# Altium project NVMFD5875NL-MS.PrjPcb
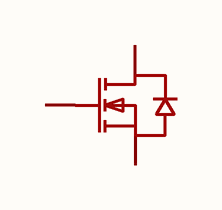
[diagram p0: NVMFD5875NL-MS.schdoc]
1 sheet, 1 parts. Net scope: global (net labels, ports and power ports of the same name join across sheets).

## Sheet NVMFD5875NL-MS.schdoc
size 127 x 101 mm

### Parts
Q?  nvmfd5875nl-ms  [TDSON-8-4_IPG20N06S4L26]  (value not drawn)  (part A of 2)

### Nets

Not connected (* = marked no-connect by the designer): Q? 1(S) 2(G) 6(D)

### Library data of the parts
Q? = nvmfd5875nl-ms: 数量:2个N沟道;漏源电压(Vdss):60V;连续漏极电流(Id):35A;导通电阻(RDS(on)):11mΩ@10V;耗散功率(Pd):60W;阈值电压(Vgs(th)):1.6V;; Manufacturer: MSKSEMI(美森科); AddInBom: yes; ModelId: 7b57ce7acef9460a94d25fd72c475b45; ModelTransform: 212.9917,253.9365,0,270,0,0,36.811,0,0; Number: 2个N沟道; Drain to Source Voltage: 60V; Current - Continuous Drain(Id): 35A; Pd - Power Dissipation: 60W; Gate Threshold Voltage (Vgs(th)): 1.6V; Gate Charge(Qg): 22nC; Input Capacitance(Ciss): 930pF; Reverse Transfer Capacitance (Crss@Vds): 8pF; Type: N沟道; Output Capacitance(Coss): 230pF; Vgs: ±20V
